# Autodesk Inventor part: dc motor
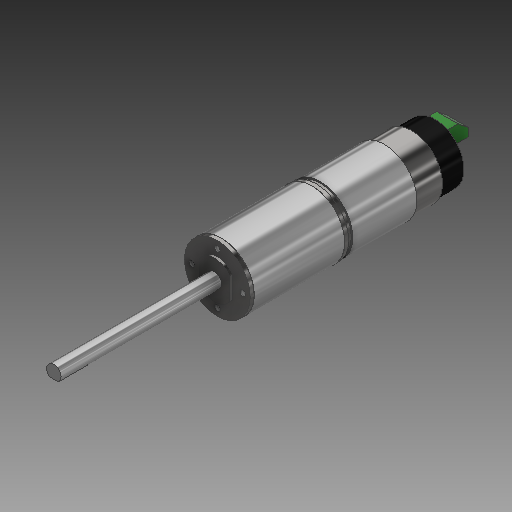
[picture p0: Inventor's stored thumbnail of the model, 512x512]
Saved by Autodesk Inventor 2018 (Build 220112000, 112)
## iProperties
Created: 2023-12
Part Number: dc motor
Material: Generic
Document SubType Name: Modeling
Designer: DDUGKY
Density: 1 g/cm^3
Appearance: Default
Author: DDUGKY
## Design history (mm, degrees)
sketch "Sketch1"
  geometry: C1 r 21.265 at (0, 0); 1 further point
  constraints: 1 centre point, 1 coincident
  dimensions: "d0" = 42.53 diameter of C1
extrude "Extrusion1" new body sketch "Sketch1" distance "d1" = 65.5; taper "d2" = 0 deg
sketch "Sketch2"
  geometry: C1 r 22.5 at (0, 0); 1 further point
  constraints: 1 centre point, 1 coincident
  dimensions: "d3" = 45 diameter of C1
extrude "Extrusion2" join sketch "Sketch2" distance "d4" = 67.5; taper "d5" = 0 deg
sketch "Sketch3"
  geometry: C1 r 20 at (0, 0); 1 further point
  constraints: 1 centre point, 1 coincident
  dimensions: "d6" = 40 diameter of C1
extrude "Extrusion3" join sketch "Sketch3" distance "d7" = 16; taper "d8" = 0 deg
workplane "Work Plane1"
sketch "Sketch4"
  geometry: L1 (21.733, -4.769)-(20.723, -4.769); L2 (20.723, 4.769)-(21.733, 4.769); A1 r 21.265 centre (0, 0) between (20.723, 4.769) and (20.723, -4.769); A2 r 22.25 centre (0, 0) between (21.733, 4.769) and (21.733, -4.769); 1 further point
  constraints: 4 end point, 4 point on circle, 2 centre point, 2 coincident, 1 horizontal, 1 parallel
  dimensions: "d10" = 42.53 diameter of A1
extrude "Extrusion4" join sketch "Sketch4" distance "d12" = 44; taper "d13" = 0 deg
workplane "Work Plane2"
sketch "Sketch5"
  geometry: C1 r 22.625 at (0, 0); 1 further point
  constraints: 1 centre point, 1 coincident
  dimensions: "d15" = 45.25 diameter of C1
extrude "Extrusion5" join sketch "Sketch5" stored distance "d16" = 62; taper "d17" = 0 deg
sketch "Sketch6"
  geometry: L1 (10.39, 7.813)-(10.39, -7.813); L2 (-10.39, -7.813)-(-10.39, 7.813); A1 r 13 centre (0, 0) between (-10.39, -7.813) and (10.39, -7.813); A2 r 13 centre (0, 0) between (10.39, 7.813) and (-10.39, 7.813); 1 further point
  constraints: 4 end point, 4 point on circle, 2 centre point, 1 coincident, 1 parallel
extrude "Extrusion6" join sketch "Sketch6" distance "d19" = 2; taper "d20" = 0 deg
sketch "Sketch7" dims "d47" = 35
  geometry: C1 r 2 at (0, 17.5); 2 further points
  constraints: 1 centre point, 1 coincident, 1 vertical alignment, 2 other
  dimensions: "d21" = 4 diameter of C1
extrude "Extrusion7" cut sketch "Sketch7" distance "d22" = 5; taper "d23" = 0 deg
pattern_circular "Circular Pattern1" dims angle "d25" = 360 deg
sketch "Sketch8"
  geometry: C1 r 5 at (0, 0); 1 further point
  constraints: 1 centre point, 1 coincident
  dimensions: "d27" = 10 diameter of C1
extrude "Extrusion8" join sketch "Sketch8" distance "d28" = 110; taper "d29" = 0 deg
sketch "Sketch9"
  geometry: L1 (3.19, -3.851)-(-3.19, -3.851); A1 r 5 centre (0, 0) between (-3.19, -3.851) and (3.19, -3.851); A2 r 5 centre (0, 0) between (3.19, -3.851) and (-3.19, -3.851) reference; 1 further point
  constraints: 4 point on circle, 2 end point, 1 centre point, 1 coincident, 1 horizontal
extrude "Extrusion9" cut sketch "Sketch9" distance "d30" = 20; taper "d31" = 0 deg
sketch "Sketch10"
  geometry: L1 (-7.315, 16.494)-(7.315, 16.494); L2 (7.315, 16.494)-(7.315, 5.184); L3 (7.315, 5.184)-(-7.315, 5.184); L4 (-7.315, 5.184)-(-7.315, 16.494); L5 (-7.315, 16.494)-(7.315, 5.184); L6 (7.315, 16.494)-(-7.315, 5.184); 2 further points
  constraints: 12 end point, 2 midpoint, 2 parallel, 1 horizontal, 1 perpendicular
  dimensions: "d32" = 14.63 distance of L2.end L3.end; "d33" = 11.31 distance of L1.end L2.end
extrude "Extrusion10" join sketch "Sketch10" distance "d34" = 16; taper "d35" = 0 deg
chamfer "Chamfer1" distance "d36" = 5.95; stored, may be unused: second distance "d37" = 7.4, angle "d38" = 45 deg
thread "Thread1" dims "d39" = 10, "d40" = 0
thread "Thread2" dims "d41" = 10, "d42" = 0
thread "Thread3" dims "d43" = 10, "d44" = 0
thread "Thread4" dims "d45" = 10, "d46" = 0
body "Solid1"
other parameters: "d9" = -18.5, "d11" = 44.5, "d14" = -33.75, "d18" = 26
